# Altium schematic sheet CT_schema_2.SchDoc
size 396 x 205 mm
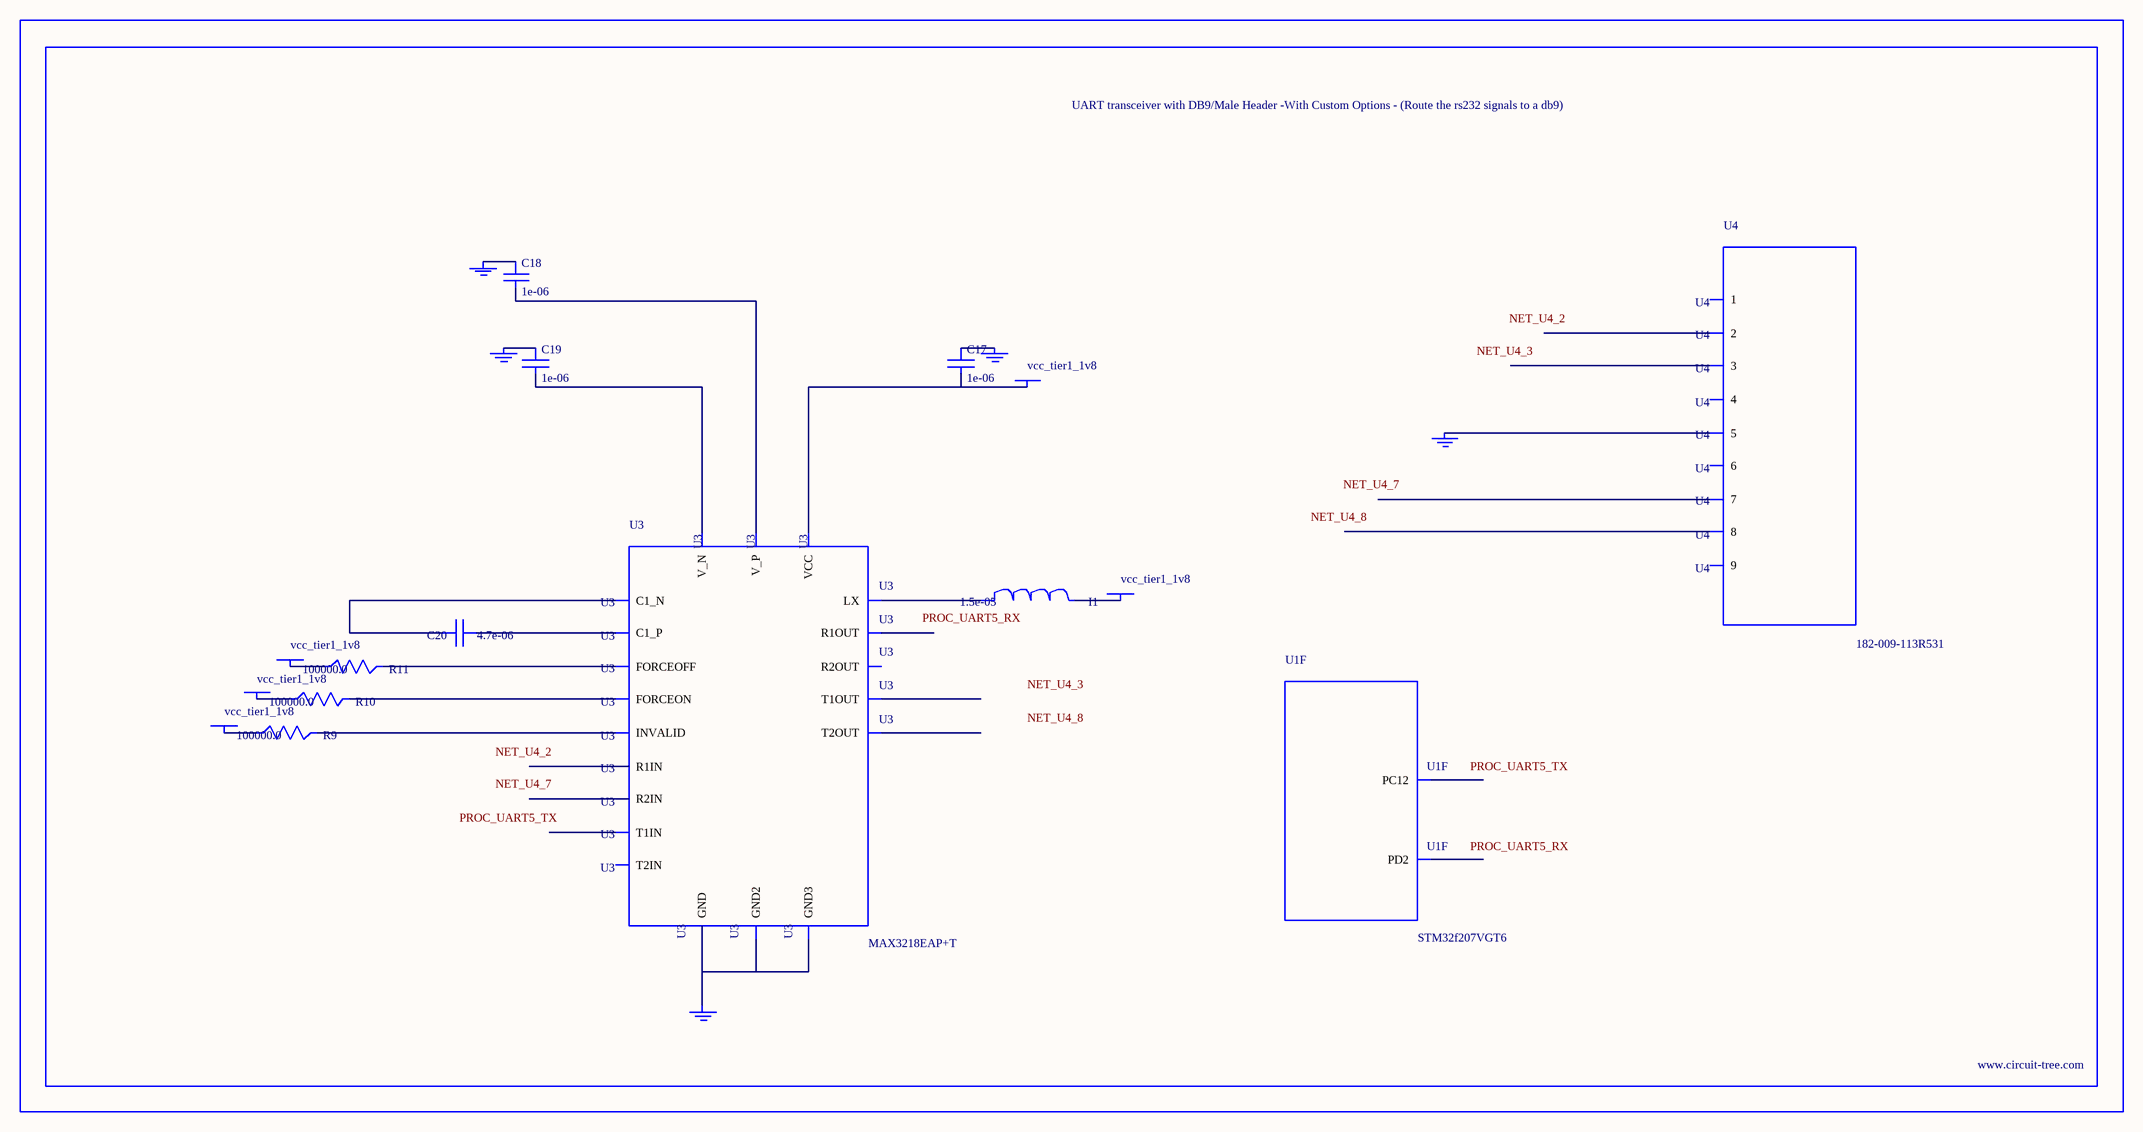
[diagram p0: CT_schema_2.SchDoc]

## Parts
BORDER1  (no value)
C17  1e-06  [C0603]
C18  1e-06  [C0603]
C19  1e-06  [C0603]
C20  4.7e-06  [C0805]
GND_INSTANCE_1_0  (no value)
GND_INSTANCE_1_1  (no value)
GND_INSTANCE_1_2  (no value)
GND_INSTANCE_1_3  (no value)
GND_INSTANCE_1_4  (no value)
I1  1.5e-05  [L1210]
POWER_INSTANCE_1_0  vcc_tier1_1v8
POWER_INSTANCE_1_1  vcc_tier1_1v8
POWER_INSTANCE_1_2  vcc_tier1_1v8
POWER_INSTANCE_1_3  vcc_tier1_1v8
POWER_INSTANCE_1_4  vcc_tier1_1v8
R9  100000.0  [R0603]
R10  100000.0  [R0603]
R11  100000.0  [R0603]
U1  STM32f207VGT6  [LQFP100]  (part F of 10)
U3  MAX3218EAP+T  [SSOP-20]
U4  182-009-113R531  [182-009-MALE]

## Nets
NetC17_1: C17.1 GND_INSTANCE_1_0.0(GND)
NetC17_2: C17.2 POWER_INSTANCE_1_4.0(PWR) U3.6(VCC)
NetC18_1: C18.1 GND_INSTANCE_1_2.0(GND)
NetC18_2: C18.2 U3.19(V_P)
NetC19_1: C19.1 GND_INSTANCE_1_1.0(GND)
NetC19_2: C19.2 U3.15(V_N)
NetC20_1: C20.1 U3.18(C1_P)
NetC20_2: C20.2 U3.16(C1_N)
NetGND_INSTANCE_1_3_0: GND_INSTANCE_1_3.0(GND) U3.5(GND) U3.17(GND2) U3.20(GND3)
NetGND_INSTANCE_1_4_0: GND_INSTANCE_1_4.0(GND) U4.5
NetI1_1: I1.1 U3.1(LX)
NetI1_2: I1.2 POWER_INSTANCE_1_0.0(PWR)
NetPOWER_INSTANCE_1_1_0: POWER_INSTANCE_1_1.0(PWR) R9.1
NetPOWER_INSTANCE_1_2_0: POWER_INSTANCE_1_2.0(PWR) R10.1
NetPOWER_INSTANCE_1_3_0: POWER_INSTANCE_1_3.0(PWR) R11.1
NetR9_2: R9.2 U3.2(INVALID)
NetR10_2: R10.2 U3.3(FORCEON)
NetR11_2: R11.2 U3.4(FORCEOFF)

Not connected (* = marked no-connect by the designer): U1 80(PC12) 83(PD2); U3 7(T1IN) 8(T2IN) 9(R1OUT) 10(R2OUT) 11(R2IN) 12(R1IN) 13(T2OUT) 14(T1OUT); U4 1 2 3 4 6 7 8 9

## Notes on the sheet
- Labels drawn without touching a wire or pin: NET_U4_2, NET_U4_3, NET_U4_7, NET_U4_8, PROC_UART5_RX, PROC_UART5_TX

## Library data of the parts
BORDER1 = BORDER_PAGE1
C17-C19 = C0603C105K3RACTU
C20 = C0805C475K4RACTU
GND_INSTANCE_1_0-GND_INSTANCE_1_4 = GND
I1 = L1210R150MDWIT
POWER_INSTANCE_1_0-POWER_INSTANCE_1_4 = PWR
R9-R11 = RC0603JR-07100KL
